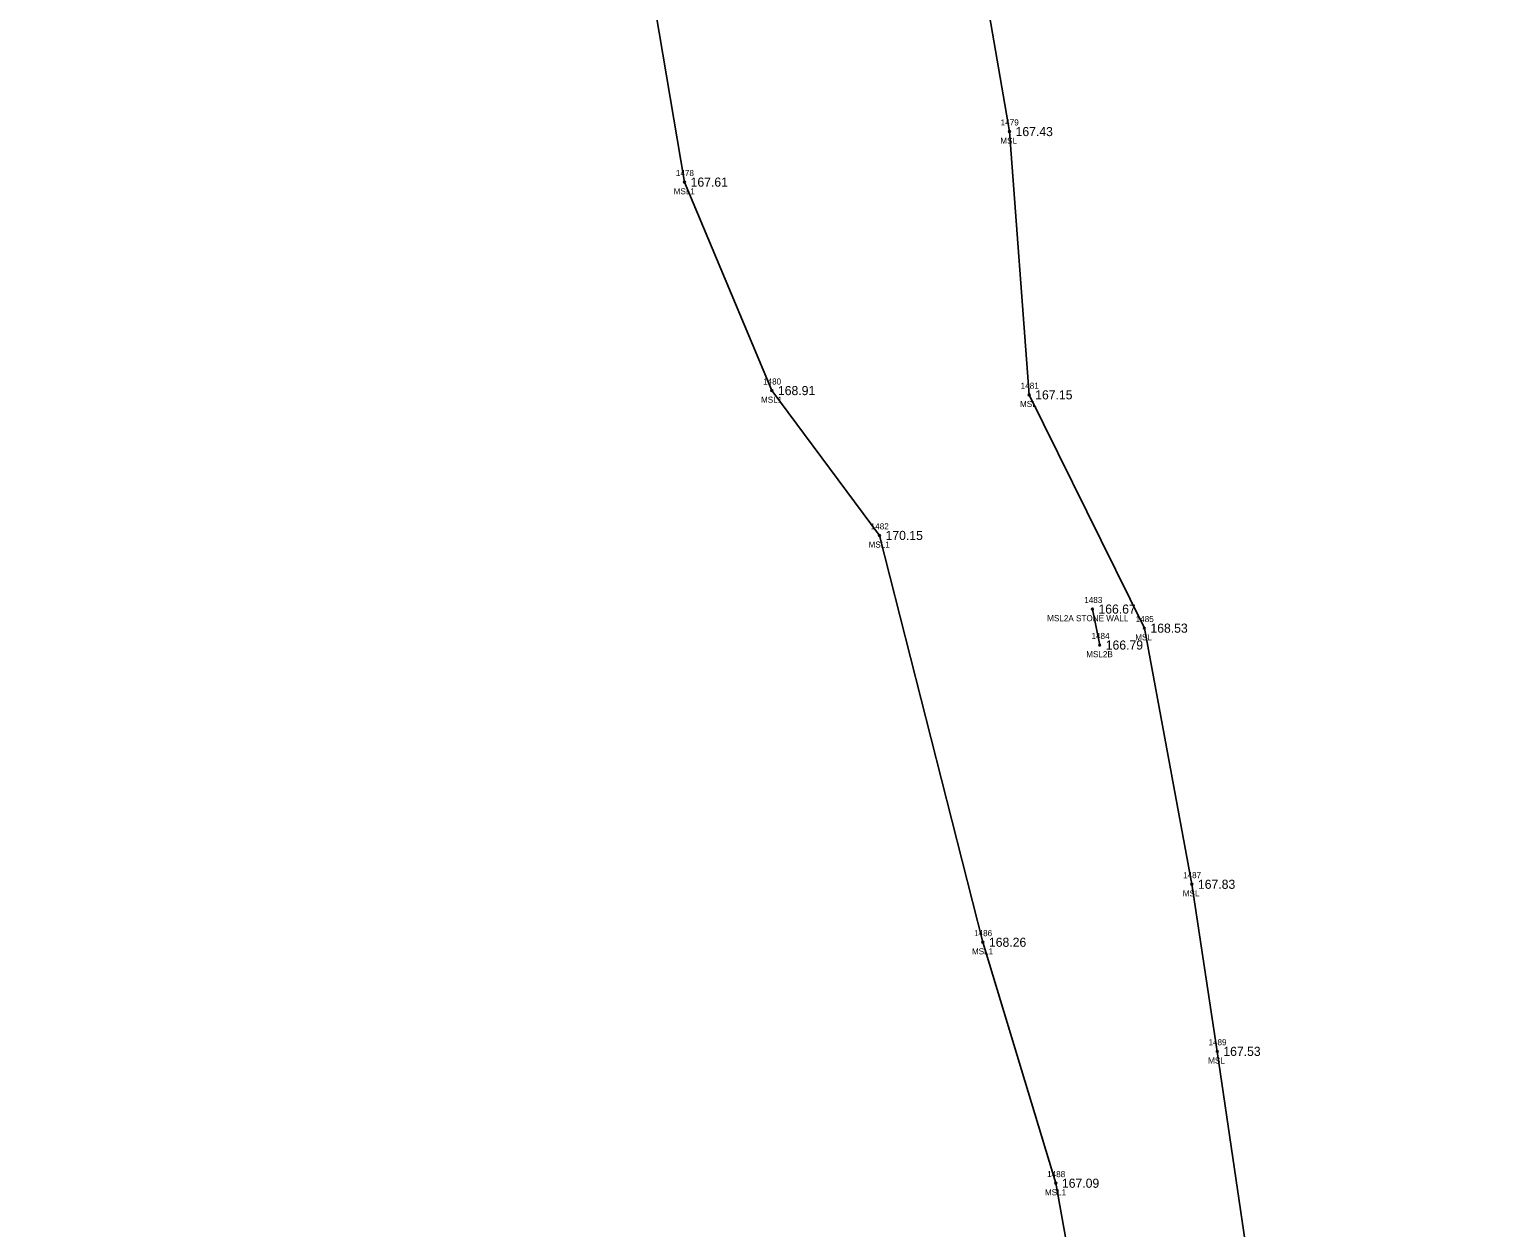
# Model space of a CAD drawing. Extents: x 1969685 to 1970577, y 796315 to 797503.
# Drawn here: x 1970128.7 to 1970371.8, y 796512 to 796709.2 of the extents above; entities that cross this region are included whole.
import ezdxf

# ---------------------------------------------------------------- set-up
doc = ezdxf.new("R2010")
doc.units = 0
for name, color, linetype in [('RD_EX_Misc', 7, 'Continuous'), ('RD_EX_Misc_txCode', 7, 'Continuous'), ('RD_EX_TX_Misc_ELEV', 7, 'Continuous'), ('RD_SMD_Locator', 7, 'Continuous')]:
    doc.layers.add(name, color=color, linetype=linetype)

msp = doc.modelspace()

# ---------------------------------------------------------------- linework, layer by layer
at = {"layer": 'RD_EX_Misc'}
msp.add_line((1970303.62, 796613.78), (1970304.82, 796607.86), dxfattribs=at)
for points in [[(1970119.68, 797002.07), (1970134.67, 796985.14), (1970155.26, 796957.98), (1970184.14, 796927.08), (1970200, 796908.86), (1970214.83, 796881.9), (1970223.07, 796860.85), (1970237.12, 796840.22), (1970247.97, 796828.57), (1970264.98, 796797.04), (1970268.55, 796760.45), (1970285.4, 796719.08), (1970289.98, 796692.37), (1970293.21, 796649.04), (1970312.17, 796610.64), (1970319.99, 796568.49), (1970324.17, 796540.99), (1970330.09, 796500.77), (1970344.67, 796440.73), (1970352.86, 796398.26), (1970358.68, 796366.34), (1970371.75, 796316.87)], [(1970114.12, 796963.3), (1970132.42, 796938.45), (1970155.62, 796908.35), (1970168.41, 796889.26), (1970180.37, 796861.1), (1970188.98, 796848.46), (1970192.73, 796834.16), (1970222.29, 796768.03), (1970236.51, 796684.05), (1970250.88, 796649.74), (1970268.59, 796625.9), (1970285.6, 796558.95), (1970297.61, 796519.29), (1970305.78, 796473.65), (1970318, 796423.32), (1970326.24, 796374.48), (1970344.95, 796321.79)]]:
    msp.add_lwpolyline(points, dxfattribs=at)
at = {"layer": 'RD_SMD_Locator'}
for centre in [(1970289.98, 796692.37), (1970236.51, 796684.05), (1970250.88, 796649.74), (1970293.21, 796649.04), (1970268.59, 796625.9), (1970303.62, 796613.78), (1970312.17, 796610.64), (1970304.82, 796607.86), (1970319.99, 796568.49), (1970285.6, 796558.95), (1970324.17, 796540.99), (1970297.61, 796519.29)]:
    msp.add_circle(centre, 0.15, dxfattribs=at)

# ---------------------------------------------------------------- texts
at = {"layer": 'RD_EX_Misc_txCode'}
for s, p in [('1479', (1970288.53, 796693.37)), ('MSL', (1970288.47, 796690.37)), ('1478', (1970235.08, 796685.05)), ('MSL1', (1970234.72, 796682.05)), ('1480', (1970249.43, 796650.74)), ('1481', (1970291.82, 796650.04)), ('MSL1', (1970249.09, 796647.74)), ('MSL', (1970291.71, 796647.04)), ('1482', (1970267.14, 796626.9)), ('MSL1', (1970266.79, 796623.9)), ('1483', (1970302.28, 796614.78)), ('MSL2A STONE WALL', (1970296.17, 796611.78)), ('1485', (1970310.74, 796611.64)), ('1484', (1970303.47, 796608.86)), ('MSL', (1970310.66, 796608.64)), ('MSL2B', (1970302.6, 796605.86)), ('1487', (1970318.54, 796569.49)), ('MSL', (1970318.49, 796566.49)), ('1486', (1970284.15, 796559.95)), ('MSL1', (1970283.8, 796556.95)), ('1489', (1970322.72, 796541.99)), ('MSL', (1970322.66, 796538.99)), ('1488', (1970296.17, 796520.29)), ('MSL1', (1970295.81, 796517.29))]:
    msp.add_text(s, height=1, dxfattribs=at).set_placement(p)
at = {"layer": 'RD_EX_TX_Misc_ELEV'}
for s, p in [('167.43', (1970290.98, 796691.62)), ('167.61', (1970237.51, 796683.3)), ('168.91', (1970251.88, 796648.99)), ('167.15', (1970294.21, 796648.29)), ('170.15', (1970269.59, 796625.15)), ('166.67', (1970304.62, 796613.03)), ('168.53', (1970313.17, 796609.89)), ('166.79', (1970305.82, 796607.11)), ('167.83', (1970320.99, 796567.74)), ('168.26', (1970286.6, 796558.2)), ('167.53', (1970325.17, 796540.24)), ('167.09', (1970298.61, 796518.54))]:
    msp.add_text(s, height=1.5, dxfattribs=at).set_placement(p)

doc.saveas('drawing.dxf')
